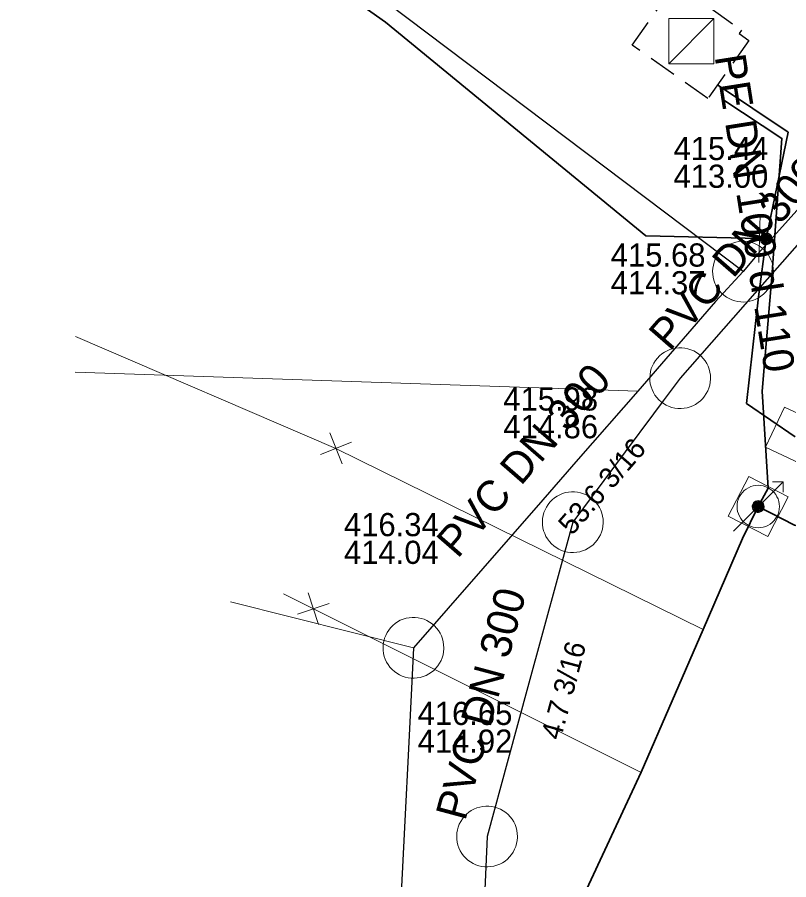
# Model space of a CAD drawing. Extents: x -772952 to -772403, y -1033777 to -1033210.
# Drawn here: x -772900.62 to -772870.65, y -1033589.93 to -1033556.43 of the extents above; entities that cross this region are included whole.
import ezdxf

# ---------------------------------------------------------------- set-up
doc = ezdxf.new("R2010")
doc.units = 0
doc.header["$LTSCALE"] = 0.36
doc.linetypes.add('MEDIUM_DASHED', pattern=[4.5, 3, -1.5])
for name, color, linetype, lineweight in [('15', 7, 'Continuous', 13), ('16', 7, 'Continuous', 35), ('18', 7, 'Continuous', 13), ('2', 7, 'Continuous', 25), ('20', 7, 'Continuous', 13), ('21', 7, 'Continuous', 13), ('24', 7, 'MEDIUM_DASHED', 25), ('4', 7, 'Continuous', 13), ('57', 7, 'Continuous', 13), ('59', 7, 'Continuous', 13)]:
    doc.layers.add(name, color=color, linetype=linetype, lineweight=lineweight)
for name, color, linetype in [('17', 7, 'Continuous'), ('3', 7, 'Continuous'), ('6', 7, 'Continuous')]:
    doc.layers.add(name, color=color, linetype=linetype)

msp = doc.modelspace()

# ---------------------------------------------------------------- linework, layer by layer
at = {"layer": '15'}
for p, q in [((-772871.811, -1033565.963), (-772871.768, -1033564.101)), ((-772888.002, -1033573.778), (-772888.477, -1033572.578)), ((-772887.636, -1033572.939), (-772888.845, -1033573.421)), ((-772888.912, -1033580.014), (-772889.318, -1033578.789)), ((-772888.499, -1033579.198), (-772889.734, -1033579.61))]:
    msp.add_line(p, q, dxfattribs=at)
for points in [[(-772871.299, -1033565.04), (-772871.305, -1033564.988), (-772871.322, -1033564.938), (-772871.351, -1033564.894), (-772871.388, -1033564.857), (-772871.433, -1033564.83), (-772871.483, -1033564.813), (-772871.536, -1033564.809), (-772871.588, -1033564.816), (-772871.637, -1033564.835), (-772871.68, -1033564.864), (-772871.716, -1033564.903), (-772871.742, -1033564.948), (-772871.758, -1033564.999), (-772871.761, -1033565.051), (-772871.753, -1033565.103), (-772871.733, -1033565.152), (-772871.702, -1033565.195), (-772871.663, -1033565.229), (-772871.617, -1033565.255), (-772871.566, -1033565.269), (-772871.513, -1033565.271), (-772871.462, -1033565.261), (-772871.414, -1033565.24), (-772871.371, -1033565.209), (-772871.337, -1033565.168), (-772871.313, -1033565.122), (-772871.301, -1033565.071)], [(-772871.329, -1033565.04), (-772871.335, -1033564.991), (-772871.352, -1033564.945), (-772871.38, -1033564.905), (-772871.417, -1033564.873), (-772871.461, -1033564.851), (-772871.509, -1033564.84), (-772871.558, -1033564.84), (-772871.605, -1033564.853), (-772871.648, -1033564.877), (-772871.684, -1033564.91), (-772871.711, -1033564.951), (-772871.727, -1033564.998), (-772871.731, -1033565.047), (-772871.724, -1033565.095), (-772871.705, -1033565.14), (-772871.675, -1033565.18), (-772871.637, -1033565.211), (-772871.593, -1033565.231), (-772871.545, -1033565.241), (-772871.496, -1033565.239), (-772871.449, -1033565.224), (-772871.406, -1033565.199), (-772871.372, -1033565.165), (-772871.346, -1033565.123), (-772871.332, -1033565.076)], [(-772871.359, -1033565.04), (-772871.365, -1033564.995), (-772871.382, -1033564.953), (-772871.41, -1033564.918), (-772871.446, -1033564.891), (-772871.488, -1033564.874), (-772871.533, -1033564.869), (-772871.578, -1033564.875), (-772871.619, -1033564.894), (-772871.654, -1033564.922), (-772871.681, -1033564.959), (-772871.697, -1033565.001), (-772871.701, -1033565.046), (-772871.694, -1033565.091), (-772871.675, -1033565.132), (-772871.646, -1033565.166), (-772871.609, -1033565.192), (-772871.566, -1033565.208), (-772871.521, -1033565.211), (-772871.476, -1033565.203), (-772871.436, -1033565.183), (-772871.402, -1033565.154), (-772871.376, -1033565.116), (-772871.362, -1033565.073)], [(-772871.389, -1033565.04), (-772871.394, -1033564.999), (-772871.412, -1033564.962), (-772871.439, -1033564.931), (-772871.474, -1033564.91), (-772871.514, -1033564.899), (-772871.555, -1033564.901), (-772871.594, -1033564.914), (-772871.628, -1033564.938), (-772871.653, -1033564.97), (-772871.668, -1033565.008), (-772871.671, -1033565.049), (-772871.663, -1033565.089), (-772871.643, -1033565.125), (-772871.614, -1033565.154), (-772871.577, -1033565.173), (-772871.537, -1033565.181), (-772871.496, -1033565.177), (-772871.458, -1033565.162), (-772871.426, -1033565.136), (-772871.403, -1033565.102), (-772871.39, -1033565.063)], [(-772871.419, -1033565.04), (-772871.424, -1033565.004), (-772871.442, -1033564.972), (-772871.468, -1033564.947), (-772871.502, -1033564.932), (-772871.538, -1033564.929), (-772871.573, -1033564.937), (-772871.604, -1033564.957), (-772871.627, -1033564.985), (-772871.64, -1033565.019), (-772871.64, -1033565.056), (-772871.629, -1033565.091), (-772871.608, -1033565.12), (-772871.578, -1033565.141), (-772871.543, -1033565.151), (-772871.506, -1033565.149), (-772871.472, -1033565.135), (-772871.445, -1033565.112), (-772871.426, -1033565.08), (-772871.419, -1033565.045)], [(-772871.449, -1033565.04), (-772871.454, -1033565.009), (-772871.471, -1033564.983), (-772871.497, -1033564.966), (-772871.527, -1033564.959), (-772871.558, -1033564.963), (-772871.585, -1033564.98), (-772871.603, -1033565.004), (-772871.611, -1033565.035), (-772871.607, -1033565.065), (-772871.592, -1033565.093), (-772871.568, -1033565.112), (-772871.538, -1033565.121), (-772871.507, -1033565.118), (-772871.479, -1033565.104), (-772871.459, -1033565.08), (-772871.449, -1033565.051)], [(-772871.479, -1033565.04), (-772871.484, -1033565.016), (-772871.501, -1033564.998), (-772871.524, -1033564.989), (-772871.548, -1033564.992), (-772871.569, -1033565.006), (-772871.58, -1033565.028), (-772871.58, -1033565.053), (-772871.568, -1033565.074), (-772871.548, -1033565.088), (-772871.523, -1033565.091), (-772871.5, -1033565.082), (-772871.484, -1033565.064)], [(-772871.509, -1033565.04), (-772871.514, -1033565.025), (-772871.529, -1033565.019), (-772871.544, -1033565.023), (-772871.551, -1033565.037), (-772871.547, -1033565.052), (-772871.534, -1033565.061), (-772871.519, -1033565.058), (-772871.509, -1033565.046)], [(-772871.608, -1033575.435), (-772871.615, -1033575.383), (-772871.632, -1033575.333), (-772871.661, -1033575.289), (-772871.698, -1033575.252), (-772871.743, -1033575.225), (-772871.793, -1033575.208), (-772871.846, -1033575.204), (-772871.897, -1033575.211), (-772871.946, -1033575.23), (-772871.99, -1033575.259), (-772872.026, -1033575.298), (-772872.052, -1033575.343), (-772872.068, -1033575.394), (-772872.071, -1033575.446), (-772872.063, -1033575.498), (-772872.043, -1033575.547), (-772872.012, -1033575.59), (-772871.973, -1033575.624), (-772871.927, -1033575.65), (-772871.875, -1033575.664), (-772871.823, -1033575.666), (-772871.772, -1033575.656), (-772871.723, -1033575.635), (-772871.681, -1033575.604), (-772871.647, -1033575.563), (-772871.623, -1033575.517), (-772871.61, -1033575.466)], [(-772871.639, -1033575.435), (-772871.645, -1033575.386), (-772871.662, -1033575.34), (-772871.69, -1033575.3), (-772871.727, -1033575.268), (-772871.771, -1033575.246), (-772871.819, -1033575.235), (-772871.868, -1033575.235), (-772871.914, -1033575.248), (-772871.958, -1033575.272), (-772871.994, -1033575.305), (-772872.021, -1033575.346), (-772872.037, -1033575.393), (-772872.041, -1033575.442), (-772872.034, -1033575.49), (-772872.015, -1033575.535), (-772871.985, -1033575.575), (-772871.946, -1033575.606), (-772871.902, -1033575.626), (-772871.855, -1033575.636), (-772871.806, -1033575.634), (-772871.759, -1033575.619), (-772871.716, -1033575.594), (-772871.681, -1033575.56), (-772871.656, -1033575.518), (-772871.642, -1033575.471)], [(-772871.669, -1033575.435), (-772871.674, -1033575.39), (-772871.691, -1033575.348), (-772871.72, -1033575.313), (-772871.755, -1033575.286), (-772871.798, -1033575.269), (-772871.843, -1033575.264), (-772871.887, -1033575.27), (-772871.929, -1033575.289), (-772871.963, -1033575.317), (-772871.99, -1033575.354), (-772872.007, -1033575.396), (-772872.011, -1033575.441), (-772872.004, -1033575.486), (-772871.985, -1033575.527), (-772871.956, -1033575.561), (-772871.919, -1033575.587), (-772871.875, -1033575.603), (-772871.831, -1033575.606), (-772871.786, -1033575.598), (-772871.745, -1033575.578), (-772871.712, -1033575.549), (-772871.686, -1033575.511), (-772871.672, -1033575.468)], [(-772871.699, -1033575.435), (-772871.703, -1033575.394), (-772871.722, -1033575.357), (-772871.749, -1033575.326), (-772871.784, -1033575.305), (-772871.824, -1033575.294), (-772871.865, -1033575.296), (-772871.904, -1033575.309), (-772871.938, -1033575.333), (-772871.963, -1033575.365), (-772871.978, -1033575.403), (-772871.98, -1033575.444), (-772871.973, -1033575.484), (-772871.953, -1033575.52), (-772871.924, -1033575.549), (-772871.887, -1033575.568), (-772871.847, -1033575.576), (-772871.806, -1033575.572), (-772871.767, -1033575.557), (-772871.735, -1033575.531), (-772871.713, -1033575.497), (-772871.7, -1033575.458)], [(-772871.728, -1033575.435), (-772871.733, -1033575.399), (-772871.752, -1033575.367), (-772871.777, -1033575.342), (-772871.811, -1033575.327), (-772871.848, -1033575.324), (-772871.882, -1033575.332), (-772871.914, -1033575.352), (-772871.936, -1033575.38), (-772871.95, -1033575.414), (-772871.95, -1033575.451), (-772871.939, -1033575.486), (-772871.918, -1033575.515), (-772871.887, -1033575.536), (-772871.853, -1033575.546), (-772871.816, -1033575.544), (-772871.782, -1033575.53), (-772871.755, -1033575.507), (-772871.735, -1033575.475), (-772871.728, -1033575.44)], [(-772871.759, -1033575.435), (-772871.764, -1033575.404), (-772871.781, -1033575.378), (-772871.806, -1033575.361), (-772871.837, -1033575.354), (-772871.868, -1033575.358), (-772871.895, -1033575.375), (-772871.913, -1033575.399), (-772871.921, -1033575.43), (-772871.917, -1033575.46), (-772871.902, -1033575.488), (-772871.877, -1033575.507), (-772871.848, -1033575.516), (-772871.816, -1033575.513), (-772871.789, -1033575.499), (-772871.769, -1033575.475), (-772871.759, -1033575.446)], [(-772871.789, -1033575.435), (-772871.794, -1033575.411), (-772871.811, -1033575.393), (-772871.833, -1033575.384), (-772871.858, -1033575.387), (-772871.879, -1033575.401), (-772871.89, -1033575.423), (-772871.89, -1033575.448), (-772871.877, -1033575.469), (-772871.858, -1033575.483), (-772871.833, -1033575.486), (-772871.809, -1033575.477), (-772871.794, -1033575.459)], [(-772871.819, -1033575.435), (-772871.824, -1033575.42), (-772871.838, -1033575.414), (-772871.853, -1033575.418), (-772871.86, -1033575.432), (-772871.857, -1033575.447), (-772871.843, -1033575.456), (-772871.828, -1033575.453), (-772871.819, -1033575.441)]]:
    msp.add_lwpolyline(points, close=True, dxfattribs=at)
at = {"layer": '16'}
msp.add_line((-772871.53, -1033565.039), (-772871.79, -1033565.033), dxfattribs=at)
for points in [[(-772871.79, -1033565.033), (-772876.199, -1033564.929), (-772886.309, -1033556.62), (-772899.019, -1033547.67), (-772902.3, -1033545.62), (-772906.89, -1033544.059), (-772909.76, -1033543.28), (-772913.98, -1033542.55), (-772915.23, -1033542.289), (-772915.48, -1033542.21)], [(-772871.53, -1033565.039), (-772870.673, -1033560.899), (-772873.419, -1033559.06)], [(-772871.839, -1033575.434), (-772871.451, -1033574.727), (-772871.688, -1033570.949), (-772871.31, -1033566.515), (-772870.916, -1033561.138), (-772873.22, -1033559.625)], [(-772870.403, -1033572.723), (-772872.293, -1033571.429), (-772871.831, -1033567.296), (-772871.53, -1033565.039)], [(-772888.497, -1033769.491), (-772888.037, -1033763.55), (-772887.271, -1033741.784), (-772886.864, -1033730.232), (-772886.524, -1033720.537), (-772886.265, -1033713.186), (-772886.123, -1033710.892), (-772885.144, -1033695.171), (-772884.647, -1033687.179), (-772883.979, -1033671.67), (-772883.189, -1033653.357), (-772882.844, -1033645.361), (-772882.811, -1033644.388), (-772882.563, -1033634.359), (-772882.448, -1033629.743), (-772882.307, -1033624.035), (-772882.184, -1033619.103), (-772881.88, -1033606.815), (-772881.767, -1033602.26), (-772881.241, -1033596.171), (-772876.388, -1033585.752), (-772873.983, -1033580.212), (-772872.449, -1033576.679), (-772871.839, -1033575.434)], [(-772871.839, -1033575.434), (-772870.427, -1033576.155), (-772849.008, -1033581.096), (-772841.55, -1033584.107), (-772822.87, -1033596.07), (-772815.517, -1033599.879), (-772800.324, -1033602.374), (-772785.625, -1033603.857), (-772759.69, -1033599.467), (-772726.1, -1033595.877), (-772705.133, -1033594.197), (-772687.467, -1033594.611), (-772649.087, -1033602.85)]]:
    msp.add_lwpolyline(points, dxfattribs=at)
at = {"layer": '18'}
msp.add_line((-772873.559, -1033556.487), (-772875.309, -1033558.237), dxfattribs=at)
msp.add_lwpolyline([(-772875.309, -1033558.237), (-772873.559, -1033558.237), (-772873.559, -1033556.487), (-772875.309, -1033556.487)], close=True, dxfattribs=at)
at = {"layer": '2'}
for points in [[(-772872.43, -1033566.313), (-772887.748, -1033554.729), (-772899.887, -1033545.543), (-772908.093, -1033539.332), (-772910.4, -1033537.587)], [(-772865.89, -1033558.98), (-772869.521, -1033563.033), (-772871.824, -1033565.591), (-772872.027, -1033565.83), (-772872.43, -1033566.313)], [(-772866.3, -1033560.7), (-772867.35, -1033561.895), (-772868.261, -1033562.931), (-772870.428, -1033565.396), (-772871.974, -1033567.156), (-772874.87, -1033570.45)], [(-772872.43, -1033566.313), (-772873.499, -1033567.479), (-772876.52, -1033570.958), (-772878.83, -1033573.6), (-772880.206, -1033575.174), (-772882.539, -1033577.842), (-772885.23, -1033580.92)], [(-772874.87, -1033570.45), (-772875.53, -1033571.334), (-772875.908, -1033571.842), (-772877.009, -1033573.317), (-772879.04, -1033576.04)], [(-772879.04, -1033576.04), (-772880.785, -1033582.44), (-772881.549, -1033585.241), (-772882.37, -1033588.25)], [(-772885.23, -1033580.92), (-772885.425, -1033584.844), (-772885.564, -1033587.637), (-772885.806, -1033592.497), (-772886.08, -1033597.99), (-772886.395, -1033604.32), (-772886.471, -1033605.845), (-772887.037, -1033616.344), (-772887.401, -1033624.519), (-772887.574, -1033627.991), (-772887.68, -1033630.11)], [(-772882.37, -1033588.25), (-772883.311, -1033609.744), (-772883.39, -1033611.53)]]:
    msp.add_lwpolyline(points, dxfattribs=at)
at = {"layer": '20'}
msp.add_line((-772870.876, -1033574.472), (-772871.279, -1033574.472), dxfattribs=at)
msp.add_lwpolyline([(-772872.802, -1033576.398), (-772870.876, -1033574.472), (-772870.876, -1033574.875)], dxfattribs=at)
msp.add_lwpolyline([(-772871.015, -1033575.435), (-772871.021, -1033575.336), (-772871.039, -1033575.238), (-772871.069, -1033575.143), (-772871.11, -1033575.053), (-772871.161, -1033574.968), (-772871.222, -1033574.889), (-772871.292, -1033574.819), (-772871.371, -1033574.758), (-772871.456, -1033574.706), (-772871.546, -1033574.665), (-772871.641, -1033574.636), (-772871.739, -1033574.618), (-772871.838, -1033574.611), (-772871.937, -1033574.617), (-772872.035, -1033574.635), (-772872.13, -1033574.664), (-772872.22, -1033574.705), (-772872.306, -1033574.756), (-772872.384, -1033574.817), (-772872.454, -1033574.888), (-772872.516, -1033574.966), (-772872.567, -1033575.051), (-772872.608, -1033575.141), (-772872.638, -1033575.236), (-772872.656, -1033575.334), (-772872.663, -1033575.433), (-772872.657, -1033575.532), (-772872.639, -1033575.63), (-772872.61, -1033575.725), (-772872.569, -1033575.815), (-772872.518, -1033575.901), (-772872.457, -1033575.979), (-772872.387, -1033576.05), (-772872.309, -1033576.111), (-772872.224, -1033576.163), (-772872.134, -1033576.204), (-772872.039, -1033576.234), (-772871.942, -1033576.252), (-772871.842, -1033576.259), (-772871.743, -1033576.253), (-772871.645, -1033576.235), (-772871.55, -1033576.206), (-772871.46, -1033576.166), (-772871.374, -1033576.115), (-772871.296, -1033576.054), (-772871.225, -1033575.984), (-772871.164, -1033575.906), (-772871.112, -1033575.821), (-772871.07, -1033575.731), (-772871.04, -1033575.636), (-772871.022, -1033575.539), (-772871.015, -1033575.439)], close=True, dxfattribs=at)
at = {"layer": '21'}
for points in [[(-772870.817, -1033571.571), (-772871.554, -1033573.136), (-772869.989, -1033573.873), (-772869.252, -1033572.308)], [(-772873.005, -1033575.804), (-772871.469, -1033576.6), (-772870.673, -1033575.064), (-772872.208, -1033574.268)]]:
    msp.add_lwpolyline(points, close=True, dxfattribs=at)
at = {"layer": '24'}
msp.add_lwpolyline([(-772872.201, -1033557.331), (-772873.797, -1033559.595), (-772876.732, -1033557.521), (-772875.043, -1033555.127), (-772872.485, -1033556.935), (-772872.577, -1033557.066)], close=True, dxfattribs=at)
at = {"layer": '4'}
for points in [[(-772871.249, -1033566.313), (-772871.255, -1033566.194), (-772871.273, -1033566.077), (-772871.302, -1033565.961), (-772871.343, -1033565.85), (-772871.395, -1033565.743), (-772871.458, -1033565.642), (-772871.531, -1033565.547), (-772871.612, -1033565.461), (-772871.702, -1033565.383), (-772871.8, -1033565.314), (-772871.903, -1033565.256), (-772872.012, -1033565.209), (-772872.126, -1033565.172), (-772872.242, -1033565.147), (-772872.36, -1033565.135), (-772872.479, -1033565.134), (-772872.598, -1033565.145), (-772872.714, -1033565.168), (-772872.828, -1033565.202), (-772872.938, -1033565.248), (-772873.043, -1033565.305), (-772873.141, -1033565.372), (-772873.232, -1033565.448), (-772873.315, -1033565.533), (-772873.389, -1033565.627), (-772873.453, -1033565.727), (-772873.507, -1033565.833), (-772873.55, -1033565.944), (-772873.582, -1033566.058), (-772873.601, -1033566.176), (-772873.609, -1033566.295), (-772873.605, -1033566.413), (-772873.589, -1033566.531), (-772873.561, -1033566.647), (-772873.522, -1033566.759), (-772873.471, -1033566.867), (-772873.41, -1033566.969), (-772873.339, -1033567.065), (-772873.259, -1033567.152), (-772873.17, -1033567.232), (-772873.074, -1033567.302), (-772872.971, -1033567.362), (-772872.863, -1033567.411), (-772872.75, -1033567.449), (-772872.634, -1033567.475), (-772872.516, -1033567.49), (-772872.397, -1033567.493), (-772872.279, -1033567.484), (-772872.161, -1033567.463), (-772872.047, -1033567.43), (-772871.937, -1033567.386), (-772871.831, -1033567.331), (-772871.732, -1033567.265), (-772871.639, -1033567.19), (-772871.555, -1033567.106), (-772871.48, -1033567.014), (-772871.414, -1033566.915), (-772871.358, -1033566.81), (-772871.314, -1033566.7), (-772871.28, -1033566.586), (-772871.259, -1033566.469), (-772871.249, -1033566.35)], [(-772873.69, -1033570.45), (-772873.696, -1033570.331), (-772873.714, -1033570.214), (-772873.743, -1033570.098), (-772873.784, -1033569.987), (-772873.836, -1033569.88), (-772873.899, -1033569.779), (-772873.972, -1033569.684), (-772874.053, -1033569.598), (-772874.143, -1033569.52), (-772874.241, -1033569.451), (-772874.344, -1033569.393), (-772874.453, -1033569.346), (-772874.567, -1033569.309), (-772874.683, -1033569.284), (-772874.801, -1033569.272), (-772874.92, -1033569.271), (-772875.039, -1033569.282), (-772875.155, -1033569.305), (-772875.269, -1033569.339), (-772875.379, -1033569.385), (-772875.483, -1033569.442), (-772875.582, -1033569.509), (-772875.673, -1033569.585), (-772875.756, -1033569.67), (-772875.83, -1033569.764), (-772875.894, -1033569.864), (-772875.948, -1033569.97), (-772875.991, -1033570.081), (-772876.023, -1033570.195), (-772876.042, -1033570.313), (-772876.05, -1033570.432), (-772876.046, -1033570.55), (-772876.03, -1033570.668), (-772876.002, -1033570.784), (-772875.963, -1033570.896), (-772875.912, -1033571.004), (-772875.851, -1033571.106), (-772875.78, -1033571.202), (-772875.7, -1033571.289), (-772875.611, -1033571.369), (-772875.515, -1033571.439), (-772875.412, -1033571.499), (-772875.304, -1033571.548), (-772875.191, -1033571.586), (-772875.075, -1033571.612), (-772874.957, -1033571.627), (-772874.838, -1033571.63), (-772874.72, -1033571.621), (-772874.602, -1033571.6), (-772874.488, -1033571.567), (-772874.378, -1033571.523), (-772874.272, -1033571.468), (-772874.173, -1033571.402), (-772874.08, -1033571.327), (-772873.996, -1033571.243), (-772873.921, -1033571.151), (-772873.855, -1033571.052), (-772873.799, -1033570.947), (-772873.755, -1033570.837), (-772873.721, -1033570.723), (-772873.7, -1033570.606), (-772873.69, -1033570.487)], [(-772877.86, -1033576.04), (-772877.866, -1033575.921), (-772877.884, -1033575.804), (-772877.913, -1033575.688), (-772877.954, -1033575.577), (-772878.006, -1033575.47), (-772878.069, -1033575.369), (-772878.142, -1033575.274), (-772878.223, -1033575.188), (-772878.313, -1033575.11), (-772878.411, -1033575.041), (-772878.514, -1033574.983), (-772878.623, -1033574.936), (-772878.737, -1033574.899), (-772878.853, -1033574.874), (-772878.971, -1033574.862), (-772879.09, -1033574.861), (-772879.209, -1033574.872), (-772879.325, -1033574.895), (-772879.439, -1033574.929), (-772879.549, -1033574.975), (-772879.654, -1033575.032), (-772879.752, -1033575.099), (-772879.843, -1033575.175), (-772879.926, -1033575.26), (-772880, -1033575.354), (-772880.064, -1033575.454), (-772880.118, -1033575.56), (-772880.161, -1033575.671), (-772880.193, -1033575.785), (-772880.212, -1033575.903), (-772880.22, -1033576.022), (-772880.216, -1033576.14), (-772880.2, -1033576.258), (-772880.172, -1033576.374), (-772880.133, -1033576.486), (-772880.082, -1033576.594), (-772880.021, -1033576.696), (-772879.95, -1033576.792), (-772879.87, -1033576.879), (-772879.781, -1033576.959), (-772879.685, -1033577.029), (-772879.582, -1033577.089), (-772879.474, -1033577.138), (-772879.361, -1033577.176), (-772879.245, -1033577.202), (-772879.127, -1033577.217), (-772879.008, -1033577.22), (-772878.89, -1033577.211), (-772878.772, -1033577.19), (-772878.658, -1033577.157), (-772878.548, -1033577.113), (-772878.442, -1033577.058), (-772878.343, -1033576.992), (-772878.25, -1033576.917), (-772878.166, -1033576.833), (-772878.091, -1033576.741), (-772878.025, -1033576.642), (-772877.969, -1033576.537), (-772877.925, -1033576.427), (-772877.891, -1033576.313), (-772877.87, -1033576.196), (-772877.86, -1033576.077)], [(-772884.049, -1033580.92), (-772884.056, -1033580.801), (-772884.074, -1033580.684), (-772884.103, -1033580.568), (-772884.144, -1033580.457), (-772884.196, -1033580.35), (-772884.259, -1033580.249), (-772884.331, -1033580.154), (-772884.413, -1033580.068), (-772884.503, -1033579.99), (-772884.601, -1033579.921), (-772884.704, -1033579.863), (-772884.813, -1033579.816), (-772884.927, -1033579.779), (-772885.043, -1033579.754), (-772885.161, -1033579.742), (-772885.28, -1033579.741), (-772885.399, -1033579.752), (-772885.515, -1033579.775), (-772885.629, -1033579.809), (-772885.739, -1033579.855), (-772885.843, -1033579.912), (-772885.942, -1033579.979), (-772886.032, -1033580.055), (-772886.116, -1033580.14), (-772886.19, -1033580.234), (-772886.254, -1033580.334), (-772886.308, -1033580.44), (-772886.351, -1033580.551), (-772886.383, -1033580.665), (-772886.402, -1033580.783), (-772886.41, -1033580.902), (-772886.406, -1033581.02), (-772886.39, -1033581.138), (-772886.362, -1033581.254), (-772886.323, -1033581.366), (-772886.272, -1033581.474), (-772886.211, -1033581.576), (-772886.14, -1033581.672), (-772886.059, -1033581.759), (-772885.971, -1033581.839), (-772885.875, -1033581.909), (-772885.772, -1033581.969), (-772885.664, -1033582.018), (-772885.551, -1033582.056), (-772885.434, -1033582.082), (-772885.317, -1033582.097), (-772885.198, -1033582.1), (-772885.08, -1033582.091), (-772884.962, -1033582.07), (-772884.848, -1033582.037), (-772884.738, -1033581.993), (-772884.632, -1033581.938), (-772884.532, -1033581.872), (-772884.44, -1033581.797), (-772884.356, -1033581.713), (-772884.281, -1033581.621), (-772884.215, -1033581.522), (-772884.159, -1033581.417), (-772884.115, -1033581.307), (-772884.081, -1033581.193), (-772884.059, -1033581.076), (-772884.049, -1033580.957)], [(-772881.19, -1033588.25), (-772881.196, -1033588.131), (-772881.214, -1033588.014), (-772881.243, -1033587.898), (-772881.284, -1033587.787), (-772881.336, -1033587.68), (-772881.399, -1033587.579), (-772881.472, -1033587.484), (-772881.553, -1033587.398), (-772881.643, -1033587.32), (-772881.741, -1033587.251), (-772881.844, -1033587.193), (-772881.953, -1033587.146), (-772882.067, -1033587.109), (-772882.183, -1033587.084), (-772882.301, -1033587.072), (-772882.42, -1033587.071), (-772882.539, -1033587.082), (-772882.655, -1033587.105), (-772882.769, -1033587.139), (-772882.879, -1033587.185), (-772882.983, -1033587.242), (-772883.082, -1033587.309), (-772883.173, -1033587.385), (-772883.256, -1033587.47), (-772883.33, -1033587.564), (-772883.394, -1033587.664), (-772883.448, -1033587.77), (-772883.491, -1033587.881), (-772883.523, -1033587.995), (-772883.542, -1033588.113), (-772883.55, -1033588.232), (-772883.546, -1033588.35), (-772883.53, -1033588.468), (-772883.502, -1033588.584), (-772883.463, -1033588.696), (-772883.412, -1033588.804), (-772883.351, -1033588.906), (-772883.28, -1033589.002), (-772883.2, -1033589.089), (-772883.111, -1033589.169), (-772883.015, -1033589.239), (-772882.912, -1033589.299), (-772882.804, -1033589.348), (-772882.691, -1033589.386), (-772882.575, -1033589.412), (-772882.457, -1033589.427), (-772882.338, -1033589.43), (-772882.22, -1033589.421), (-772882.102, -1033589.4), (-772881.988, -1033589.367), (-772881.878, -1033589.323), (-772881.772, -1033589.268), (-772881.673, -1033589.202), (-772881.58, -1033589.127), (-772881.496, -1033589.043), (-772881.421, -1033588.951), (-772881.355, -1033588.852), (-772881.299, -1033588.747), (-772881.255, -1033588.637), (-772881.221, -1033588.523), (-772881.2, -1033588.406), (-772881.19, -1033588.287)]]:
    msp.add_lwpolyline(points, close=True, dxfattribs=at)
at = {"layer": '57'}
for p, q in [((-772876.52, -1033570.958), (-772898.37, -1033570.22)), ((-772885.23, -1033580.92), (-772892.34, -1033579.14))]:
    msp.add_line(p, q, dxfattribs=at)
at = {"layer": '59'}
for points in [[(-772873.983, -1033580.212), (-772888.24, -1033573.18), (-772898.354, -1033568.837)], [(-772876.391, -1033585.758), (-772889.116, -1033579.404), (-772890.271, -1033578.829)]]:
    msp.add_lwpolyline(points, dxfattribs=at)

# ---------------------------------------------------------------- texts
at = {"layer": '17'}
msp.add_text('PE DN 100 d 110 ', height=1.2, rotation=279, dxfattribs=at).set_placement((-772873.535, -1033557.959))
at = {"layer": '3'}
for s, height, rotation, p in [('PVC DN 300', 1.2, 49, (-772875.275, -1033569.439)), ('PVC DN 300', 1.2, 49, (-772883.516, -1033577.488)), ('53.6 3/16', 0.8, 49, (-772879.074, -1033576.591)), ('PVC DN 300', 1.2, 75, (-772883.22, -1033587.676)), ('4.7 3/16 ', 0.8, 75, (-772879.515, -1033584.541))]:
    msp.add_text(s, height=height, rotation=rotation, dxfattribs=at).set_placement(p)
at = {"layer": '6'}
for s, p in [('415.44', (-772875.128, -1033561.981)), ('413.00', (-772875.128, -1033563.058)), ('415.68', (-772877.568, -1033566.118)), ('414.37', (-772877.568, -1033567.195)), ('415.98', (-772881.739, -1033571.708)), ('414.86', (-772881.739, -1033572.785)), ('416.34', (-772887.928, -1033576.587)), ('414.04', (-772887.928, -1033577.664)), ('416.65', (-772885.068, -1033583.919)), ('414.92', (-772885.068, -1033584.996))]:
    msp.add_text(s, height=0.9, dxfattribs=at).set_placement(p)

doc.saveas('drawing.dxf')
